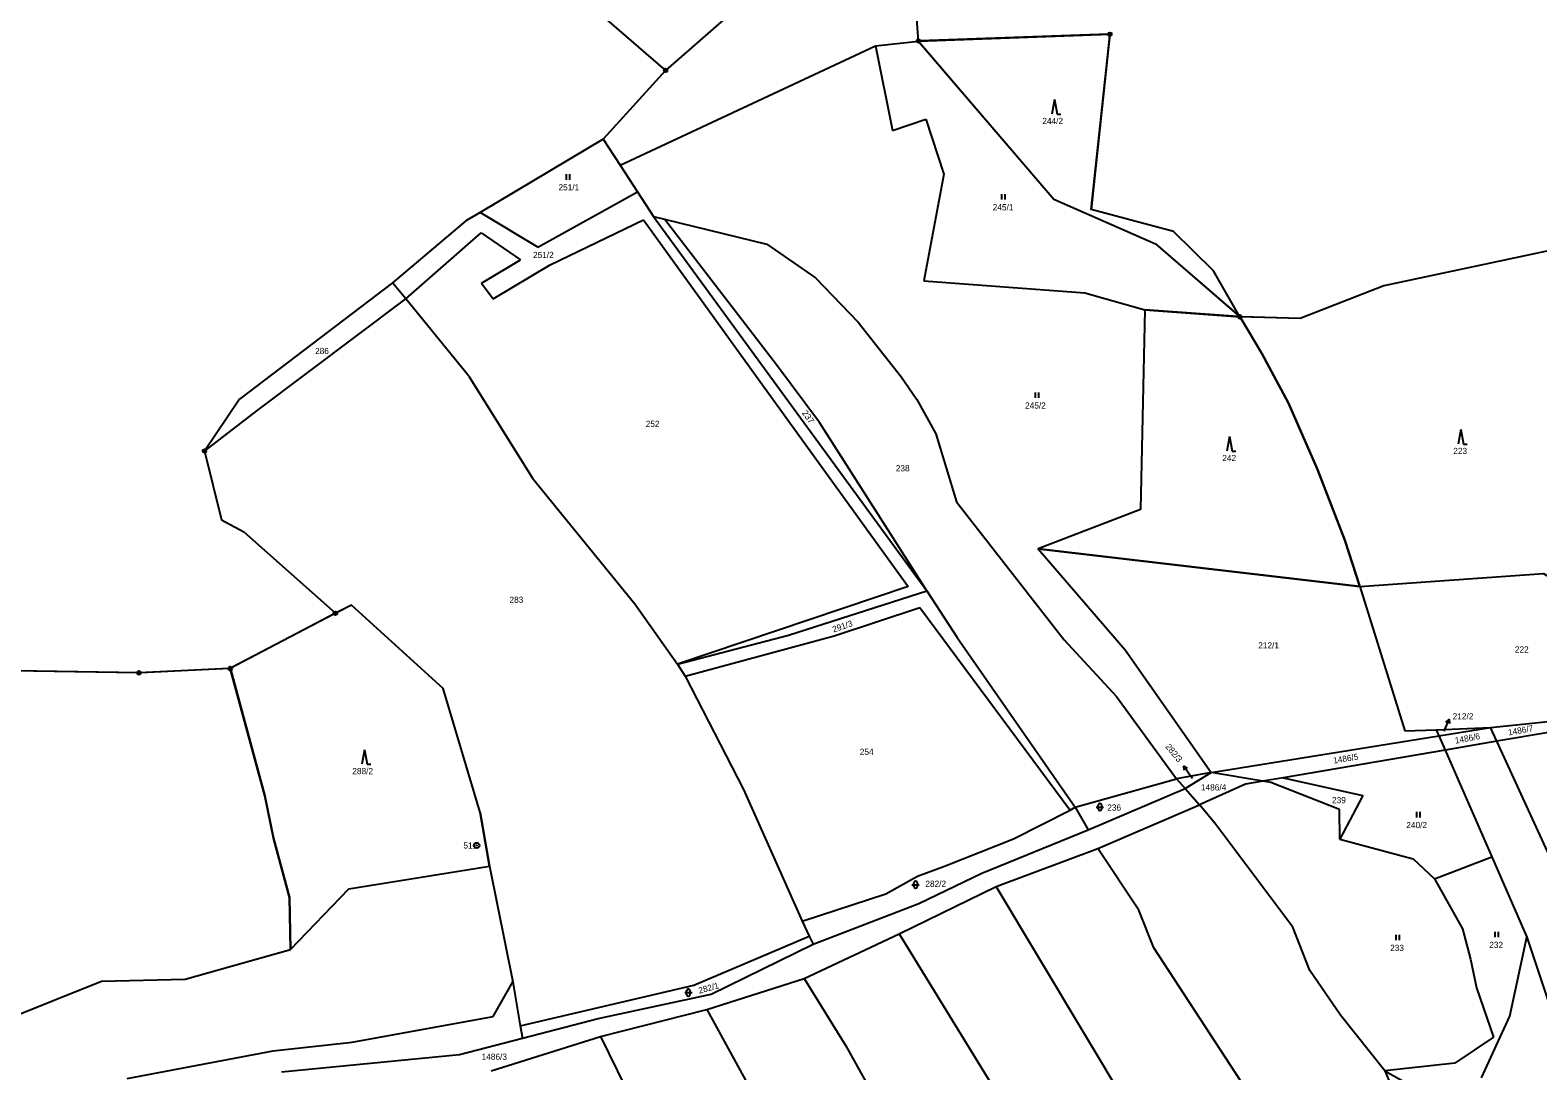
# Model space of a CAD drawing. Extents: x -760642 to -757221, y -1092371 to -1088855.
# Drawn here: x -759009.6 to -758595.9, y -1089386.3 to -1089100.6 of the extents above; entities that cross this region are included whole.
import ezdxf

# ---------------------------------------------------------------- set-up
doc = ezdxf.new("R2010")
doc.units = 0
for name, color, linetype in [('Vrstva 1', 7, 'Continuous'), ('Vrstva 13', 7, 'Continuous'), ('Vrstva 16', 7, 'Continuous'), ('Vrstva 17', 7, 'Continuous'), ('Vrstva 18', 7, 'Continuous'), ('Vrstva 24', 7, 'Continuous'), ('Vrstva 25', 7, 'Continuous'), ('Vrstva 30', 7, 'Continuous')]:
    doc.layers.add(name, color=color, linetype=linetype)

msp = doc.modelspace()

# ---------------------------------------------------------------- linework, layer by layer
at = {"layer": 'Vrstva 1'}
for p, q in [((-758806.96, -1089086.83), (-758835.2, -1089111.71)), ((-758847.72, -1089137.73), (-758777.58, -1089104.93)), ((-758777.58, -1089104.93), (-758765.86, -1089103.63)), ((-758777.58, -1089104.93), (-758772.95, -1089128.17)), ((-758765.86, -1089103.63), (-758728.69, -1089147.07)), ((-758772.95, -1089128.17), (-758763.77, -1089125.06)), ((-758763.77, -1089125.06), (-758758.83, -1089140.17)), ((-758852.39, -1089130.57), (-758847.72, -1089137.73)), ((-758847.72, -1089137.73), (-758842.96, -1089145.03)), ((-758758.83, -1089140.17), (-758764.34, -1089169.41)), ((-758870.25, -1089160.21), (-758842.96, -1089145.03)), ((-758842.96, -1089145.03), (-758838.55, -1089151.8)), ((-758728.69, -1089147.07), (-758700.81, -1089159.29)), ((-758870.25, -1089160.21), (-758886.09, -1089150.66)), ((-758866.92, -1089165.08), (-758841.31, -1089152.72)), ((-758841.31, -1089152.72), (-758809.38, -1089197)), ((-758838.55, -1089151.8), (-758835.54, -1089152.54)), ((-758838.55, -1089151.8), (-758763.58, -1089254.51)), ((-758835.54, -1089152.54), (-758807.4, -1089159.43)), ((-758804.82, -1089192.51), (-758835.54, -1089152.54)), ((-758906.54, -1089174.42), (-758885.79, -1089156.32)), ((-758885.79, -1089156.32), (-758875.06, -1089163.7)), ((-758807.4, -1089159.43), (-758794.13, -1089168.66)), ((-758700.81, -1089159.29), (-758677.66, -1089179.3)), ((-758885.71, -1089170.11), (-758875.06, -1089163.7)), ((-758882.49, -1089174.37), (-758866.92, -1089165.08)), ((-758906.54, -1089174.42), (-758910.14, -1089169.98)), ((-758885.71, -1089170.11), (-758882.49, -1089174.37)), ((-758794.13, -1089168.66), (-758782.42, -1089180.77)), ((-758764.34, -1089169.41), (-758720.16, -1089172.73)), ((-758947.37, -1089205.09), (-758906.54, -1089174.42)), ((-758889.22, -1089195.64), (-758906.54, -1089174.42)), ((-758720.16, -1089172.73), (-758703.71, -1089177.42)), ((-758703.71, -1089177.42), (-758704.9, -1089232.18)), ((-758703.71, -1089177.42), (-758677.66, -1089179.3)), ((-758677.66, -1089179.3), (-758671.58, -1089189.42)), ((-758782.42, -1089180.77), (-758770.45, -1089195.87)), ((-758793.02, -1089208.3), (-758804.82, -1089192.51)), ((-758671.58, -1089189.42), (-758664.26, -1089203.07)), ((-758889.22, -1089195.64), (-758871.78, -1089223.66)), ((-758770.45, -1089195.87), (-758766.28, -1089201.98)), ((-758809.38, -1089197), (-758768.62, -1089253.32)), ((-758961.77, -1089216.17), (-758947.37, -1089205.09)), ((-758766.28, -1089201.98), (-758761.08, -1089211.48)), ((-758664.26, -1089203.07), (-758656.38, -1089221.23)), ((-758763.58, -1089254.51), (-758793.02, -1089208.3)), ((-758761.08, -1089211.48), (-758755.35, -1089230.09)), ((-758656.38, -1089221.23), (-758648.84, -1089240.6)), ((-758871.78, -1089223.66), (-758843.69, -1089258.12)), ((-758755.35, -1089230.09), (-758725.84, -1089268)), ((-758704.9, -1089232.18), (-758732.99, -1089242.97)), ((-758648.84, -1089240.6), (-758644.74, -1089253.34)), ((-758644.74, -1089253.34), (-758732.99, -1089242.97)), ((-758732.99, -1089242.97), (-758709.08, -1089270.75)), ((-758644.74, -1089253.34), (-758594.33, -1089249.82)), ((-758768.62, -1089253.32), (-758831.96, -1089274.7)), ((-758801.49, -1089266.7), (-758763.58, -1089254.51)), ((-758763.58, -1089254.51), (-758755.18, -1089267.31)), ((-758644.74, -1089253.34), (-758632.34, -1089292.95)), ((-758921.36, -1089258.49), (-758925.81, -1089260.68)), ((-758896.27, -1089281.34), (-758921.36, -1089258.49)), ((-758843.69, -1089258.12), (-758831.96, -1089274.7)), ((-758789, -1089266.9), (-758765.5, -1089259.15)), ((-758765.5, -1089259.15), (-758724.18, -1089314.77)), ((-758831.96, -1089274.7), (-758801.49, -1089266.7)), ((-758829.82, -1089277.96), (-758789, -1089266.9)), ((-758755.18, -1089267.31), (-758722.83, -1089313.91)), ((-758725.84, -1089268), (-758711.49, -1089283.54)), ((-758709.08, -1089270.75), (-758685.49, -1089304.37)), ((-758831.96, -1089274.7), (-758829.82, -1089277.96)), ((-758945.22, -1089310.83), (-758954.69, -1089275.84)), ((-758829.82, -1089277.96), (-758813.85, -1089309.1)), ((-758886.08, -1089315.4), (-758896.27, -1089281.34)), ((-758711.49, -1089283.54), (-758695.03, -1089306.11)), ((-758623.76, -1089292.69), (-758608.87, -1089292.02)), ((-758623.05, -1089294.31), (-758608.87, -1089292.02)), ((-758608.87, -1089292.02), (-758593.08, -1089290.4)), ((-758607.09, -1089295.84), (-758608.87, -1089292.02)), ((-758685.49, -1089304.37), (-758623.05, -1089294.31)), ((-758632.34, -1089292.95), (-758623.76, -1089292.69)), ((-758623.76, -1089292.69), (-758623.05, -1089294.31)), ((-758623.05, -1089294.31), (-758621.32, -1089298.27)), ((-758607.09, -1089295.84), (-758621.32, -1089298.27)), ((-758591.9, -1089293.25), (-758607.09, -1089295.84)), ((-758578.14, -1089359.07), (-758607.09, -1089295.84)), ((-758621.32, -1089298.27), (-758665.79, -1089305.87)), ((-758621.32, -1089298.27), (-758608.54, -1089327.54)), ((-758685.49, -1089304.37), (-758695.03, -1089306.11)), ((-758692.67, -1089308.78), (-758685.49, -1089304.37)), ((-758671.3, -1089306.81), (-758685.49, -1089304.37)), ((-758722.83, -1089313.91), (-758695.03, -1089306.11)), ((-758695.03, -1089306.11), (-758692.67, -1089308.78)), ((-758676.07, -1089307.62), (-758688.72, -1089313.31)), ((-758671.3, -1089306.81), (-758676.07, -1089307.62)), ((-758665.79, -1089305.87), (-758671.3, -1089306.81)), ((-758669.17, -1089307.17), (-758671.3, -1089306.81)), ((-758650.27, -1089314.52), (-758669.17, -1089307.17)), ((-758665.79, -1089305.87), (-758643.89, -1089310.74)), ((-758942.82, -1089322.44), (-758945.22, -1089310.83)), ((-758813.85, -1089309.1), (-758797.77, -1089345.22)), ((-758719.25, -1089320.18), (-758692.67, -1089308.78)), ((-758692.67, -1089308.78), (-758688.72, -1089313.31)), ((-758643.89, -1089310.74), (-758650.21, -1089322.73)), ((-758886.08, -1089315.4), (-758883.53, -1089330.13)), ((-758739.77, -1089322.64), (-758724.18, -1089314.77)), ((-758724.18, -1089314.77), (-758722.83, -1089313.91)), ((-758722.83, -1089313.91), (-758719.25, -1089320.18)), ((-758716.63, -1089325.27), (-758688.72, -1089313.31)), ((-758684.55, -1089318.34), (-758688.72, -1089313.31)), ((-758650.21, -1089322.73), (-758650.27, -1089314.52)), ((-758748.43, -1089332.07), (-758719.25, -1089320.18)), ((-758663.08, -1089346.84), (-758684.55, -1089318.34)), ((-758938.46, -1089338.67), (-758942.82, -1089322.44)), ((-758758.67, -1089330.1), (-758739.77, -1089322.64)), ((-758650.21, -1089322.73), (-758630.08, -1089328.14)), ((-758744.55, -1089335.69), (-758716.63, -1089325.27)), ((-758705.4, -1089342.16), (-758716.63, -1089325.27)), ((-758630.08, -1089328.14), (-758624.28, -1089333.59)), ((-758624.28, -1089333.59), (-758608.54, -1089327.54)), ((-758608.54, -1089327.54), (-758598.93, -1089349.56)), ((-758922.13, -1089336.32), (-758883.53, -1089330.13)), ((-758883.53, -1089330.13), (-758877.13, -1089361.88)), ((-758774.77, -1089337.68), (-758766.12, -1089332.89)), ((-758766.12, -1089332.89), (-758758.67, -1089330.1)), ((-758765.73, -1089340.33), (-758748.43, -1089332.07)), ((-758938.12, -1089353.02), (-758922.13, -1089336.32)), ((-758771.14, -1089348.64), (-758744.55, -1089335.69)), ((-758703.81, -1089403.61), (-758744.55, -1089335.69)), ((-758624.28, -1089333.59), (-758616.57, -1089347.27)), ((-758938.12, -1089353.02), (-758938.46, -1089338.67)), ((-758797.77, -1089345.22), (-758774.77, -1089337.68)), ((-758794.75, -1089351.56), (-758765.73, -1089340.33)), ((-758797.77, -1089345.22), (-758795.81, -1089349.34)), ((-758701.29, -1089352.57), (-758705.4, -1089342.16)), ((-758827.46, -1089362.79), (-758795.81, -1089349.34)), ((-758797.2, -1089360.9), (-758771.14, -1089348.64)), ((-758795.81, -1089349.34), (-758794.75, -1089351.56)), ((-758771.14, -1089348.64), (-758744.55, -1089392.09)), ((-758658.44, -1089358.77), (-758663.08, -1089346.84)), ((-758616.57, -1089347.27), (-758614.33, -1089355.59)), ((-758603.59, -1089371.32), (-758598.93, -1089349.56)), ((-758598.93, -1089349.56), (-758590.19, -1089375.63)), ((-758967.09, -1089361.14), (-758938.12, -1089353.02)), ((-758822.69, -1089365.28), (-758794.75, -1089351.56)), ((-758671.52, -1089398.05), (-758701.29, -1089352.57)), ((-758614.33, -1089355.59), (-758612.74, -1089363.49)), ((-759016.87, -1089372.48), (-758989.96, -1089361.68)), ((-758989.96, -1089361.68), (-758967.09, -1089361.14)), ((-758882.49, -1089371.34), (-758877.13, -1089361.88)), ((-758877.13, -1089361.88), (-758875.08, -1089373.94)), ((-758823.94, -1089369.43), (-758797.2, -1089360.9)), ((-758797.2, -1089360.9), (-758785.74, -1089379.46)), ((-758650, -1089370.96), (-758658.44, -1089358.77)), ((-758875.08, -1089373.94), (-758827.46, -1089362.79)), ((-758853.69, -1089371.88), (-758822.69, -1089365.28)), ((-758612.74, -1089363.49), (-758608.08, -1089377.05)), ((-758853.05, -1089376.83), (-758823.94, -1089369.43)), ((-758823.94, -1089369.43), (-758779.56, -1089450.18)), ((-758921.25, -1089378.45), (-758882.49, -1089371.34)), ((-758875.08, -1089373.94), (-758874.51, -1089377.29)), ((-758874.51, -1089377.29), (-758853.69, -1089371.88)), ((-758637.85, -1089386.28), (-758650, -1089370.96)), ((-758611.31, -1089388.19), (-758603.59, -1089371.32)), ((-758942.91, -1089380.82), (-758921.25, -1089378.45)), ((-758891.8, -1089381.78), (-758874.51, -1089377.29)), ((-758883.06, -1089386.31), (-758853.05, -1089376.83)), ((-758853.05, -1089376.83), (-758830.77, -1089422.32)), ((-758608.08, -1089377.05), (-758618.64, -1089384.22)), ((-758982.96, -1089388.36), (-758942.91, -1089380.82)), ((-758940.61, -1089386.57), (-758891.8, -1089381.78)), ((-758785.74, -1089379.46), (-758760.41, -1089424.72)), ((-758618.64, -1089384.22), (-758637.85, -1089386.28)), ((-758637.85, -1089386.28), (-758622, -1089395.14)), ((-758637.85, -1089386.28), (-758617.78, -1089434.32))]:
    msp.add_line(p, q, dxfattribs=at)
at = {"layer": 'Vrstva 13'}
for p, q in [((-758765.86, -1089103.63), (-758768.37, -1089067.76)), ((-758864.44, -1089086.48), (-758835.2, -1089111.71)), ((-758765.86, -1089103.63), (-758713.31, -1089101.77)), ((-758713.31, -1089101.77), (-758718.42, -1089149.83)), ((-758835.2, -1089111.71), (-758852.39, -1089130.57)), ((-758852.39, -1089130.57), (-758886.09, -1089150.66)), ((-758886.09, -1089150.66), (-758889.99, -1089152.99)), ((-758695.85, -1089155.89), (-758718.42, -1089149.83)), ((-758889.99, -1089152.99), (-758910.14, -1089169.98)), ((-758684.84, -1089166.7), (-758695.85, -1089155.89)), ((-758592.14, -1089161.06), (-758638.18, -1089170.81)), ((-758677.66, -1089179.3), (-758684.84, -1089166.7)), ((-758910.14, -1089169.98), (-758952.14, -1089201.9)), ((-758638.18, -1089170.81), (-758661.09, -1089179.82)), ((-758661.09, -1089179.82), (-758677.66, -1089179.3)), ((-758952.14, -1089201.9), (-758961.77, -1089216.17)), ((-758961.77, -1089216.17), (-758957.11, -1089235.03)), ((-758957.11, -1089235.03), (-758950.91, -1089238.38)), ((-758950.91, -1089238.38), (-758925.81, -1089260.68)), ((-758925.81, -1089260.68), (-758954.69, -1089275.84)), ((-758979.74, -1089277.04), (-759077.5, -1089275.49)), ((-758954.69, -1089275.84), (-758979.74, -1089277.04))]:
    msp.add_line(p, q, dxfattribs=at)
at = {"layer": 'Vrstva 16'}
for p, q in [((-758621.36, -1089292.61), (-758620.256, -1089289.82)), ((-758621.53, -1089293.03), (-758621.36, -1089292.61)), ((-758691.34, -1089305.1), (-758693.057, -1089302.64)), ((-758690.66, -1089306.08), (-758691.34, -1089305.1))]:
    msp.add_line(p, q, dxfattribs=at)
for points in [[(-758621.089, -1089290.566), (-758620.256, -1089289.82), (-758620.159, -1089290.934)], [(-758692.894, -1089303.746), (-758693.057, -1089302.64), (-758692.074, -1089303.174)]]:
    msp.add_lwpolyline(points, dxfattribs=at)
at = {"layer": 'Vrstva 24'}
for centre, radius in [((-758713.31, -1089101.77), 0.5), ((-758713.31, -1089101.77), 0.0327), ((-758765.86, -1089103.63), 0.5), ((-758765.86, -1089103.63), 0.5), ((-758765.86, -1089103.63), 0.0327), ((-758765.86, -1089103.63), 0.0327), ((-758835.2, -1089111.71), 0.5), ((-758835.2, -1089111.71), 0.0327), ((-758677.66, -1089179.3), 0.5), ((-758677.66, -1089179.3), 0.5), ((-758677.66, -1089179.3), 0.0327), ((-758677.66, -1089179.3), 0.0327), ((-758961.77, -1089216.17), 0.5), ((-758961.77, -1089216.17), 0.0327), ((-758925.81, -1089260.68), 0.5), ((-758925.81, -1089260.68), 0.0327), ((-758954.69, -1089275.84), 0.5), ((-758954.69, -1089275.84), 0.5), ((-758979.74, -1089277.04), 0.5), ((-758979.74, -1089277.04), 0.5), ((-758979.74, -1089277.04), 0.0327), ((-758979.74, -1089277.04), 0.0327), ((-758954.69, -1089275.84), 0.0327), ((-758954.69, -1089275.84), 0.0327), ((-758887.05, -1089324.42), 0.75), ((-758887.05, -1089324.42), 0.0327)]:
    msp.add_circle(centre, radius, dxfattribs=at)
at = {"layer": 'Vrstva 25'}
for p, q in [((-758728.542, -1089119.709), (-758729.275, -1089123.709)), ((-758728.542, -1089119.709), (-758727.809, -1089123.709)), ((-758727.809, -1089123.709), (-758726.809, -1089123.709)), ((-758862.507, -1089140.195), (-758862.507, -1089141.695)), ((-758861.485, -1089141.695), (-758861.485, -1089140.195)), ((-758743.047, -1089145.675), (-758743.047, -1089147.175)), ((-758742.025, -1089147.175), (-758742.025, -1089145.675)), ((-758733.797, -1089200.085), (-758733.797, -1089201.585)), ((-758732.775, -1089201.585), (-758732.775, -1089200.085)), ((-758680.472, -1089212.219), (-758681.205, -1089216.219)), ((-758680.472, -1089212.219), (-758679.739, -1089216.219)), ((-758617.022, -1089210.289), (-758617.755, -1089214.289)), ((-758617.022, -1089210.289), (-758616.289, -1089214.289)), ((-758679.739, -1089216.219), (-758678.739, -1089216.219)), ((-758616.289, -1089214.289), (-758615.289, -1089214.289)), ((-758917.832, -1089298.149), (-758918.565, -1089302.149)), ((-758917.832, -1089298.149), (-758917.099, -1089302.149)), ((-758917.099, -1089302.149), (-758916.099, -1089302.149)), ((-758717.03, -1089313.87), (-758715.03, -1089313.87)), ((-758716.53, -1089314.37), (-758716.53, -1089313.37)), ((-758715.53, -1089314.37), (-758715.53, -1089313.37)), ((-758629.207, -1089315.235), (-758629.207, -1089316.735)), ((-758628.185, -1089316.735), (-758628.185, -1089315.235)), ((-758767.61, -1089335.19), (-758765.61, -1089335.19)), ((-758767.11, -1089335.69), (-758767.11, -1089334.69)), ((-758766.11, -1089335.69), (-758766.11, -1089334.69)), ((-758634.887, -1089348.955), (-758634.887, -1089350.455)), ((-758633.865, -1089350.455), (-758633.865, -1089348.955)), ((-758607.697, -1089348.135), (-758607.697, -1089349.635)), ((-758606.675, -1089349.635), (-758606.675, -1089348.135)), ((-758829.97, -1089364.81), (-758827.97, -1089364.81)), ((-758829.47, -1089365.31), (-758829.47, -1089364.31)), ((-758828.47, -1089365.31), (-758828.47, -1089364.31))]:
    msp.add_line(p, q, dxfattribs=at)
for centre, start, end in [((-758716.03, -1089313.37), 0, 180), ((-758716.03, -1089314.37), 180, 0), ((-758766.61, -1089334.69), 0, 180), ((-758766.61, -1089335.69), 180, 0), ((-758828.97, -1089364.31), 0, 180), ((-758828.97, -1089365.31), 180, 0)]:
    msp.add_arc(centre, 0.5, start, end, dxfattribs=at)
at = {"layer": 'Vrstva 30'}
for points in [[(-758713.81, -1089101.788), (-758765.36, -1089103.612)], [(-758765.535, -1089104.01), (-758728.69, -1089147.07), (-758700.81, -1089159.29), (-758678.038, -1089178.973)], [(-758677.908, -1089178.866), (-758684.84, -1089166.7), (-758695.85, -1089155.89), (-758718.42, -1089149.83), (-758713.363, -1089102.267)], [(-758677.403, -1089179.729), (-758671.58, -1089189.42), (-758664.26, -1089203.07), (-758656.38, -1089221.23), (-758648.84, -1089240.6), (-758644.74, -1089253.34), (-758594.33, -1089249.82), (-758582.08, -1089257.06), (-758568.43, -1089249.17), (-758592.01, -1089161.543), (-758592.14, -1089161.06), (-758638.18, -1089170.81), (-758661.09, -1089179.82), (-758677.16, -1089179.316)], [(-758678.159, -1089179.264), (-758703.71, -1089177.42), (-758704.9, -1089232.18), (-758732.99, -1089242.97), (-758644.74, -1089253.34), (-758648.84, -1089240.6), (-758656.38, -1089221.23), (-758664.26, -1089203.07), (-758671.58, -1089189.42), (-758677.403, -1089179.729)], [(-758954.559, -1089276.323), (-758945.22, -1089310.83), (-758942.82, -1089322.44), (-758938.46, -1089338.67), (-758938.12, -1089353.02), (-758922.13, -1089336.32), (-758883.53, -1089330.13), (-758886.08, -1089315.4), (-758896.27, -1089281.34), (-758921.36, -1089258.49), (-758925.361, -1089260.459)], [(-758926.253, -1089260.912), (-758954.247, -1089275.608)], [(-759260.604, -1089266.083), (-759261.13, -1089269.16), (-759262.38, -1089276.56), (-759244.75, -1089308.25), (-759118.13, -1089341.69), (-759091.99, -1089341), (-759071.08, -1089368.72), (-759046.58, -1089377.41), (-759016.87, -1089372.48), (-758989.96, -1089361.68), (-758967.09, -1089361.14), (-758938.12, -1089353.02), (-758938.46, -1089338.67), (-758942.82, -1089322.44), (-758945.22, -1089310.83), (-758954.559, -1089276.323)], [(-758980.24, -1089277.032), (-759077, -1089275.498)], [(-758955.189, -1089275.864), (-758979.241, -1089277.016)]]:
    msp.add_lwpolyline(points, dxfattribs=at)
for centre, start, end in [((-758713.31, -1089101.77), 182.02713, 263.9308), ((-758765.86, -1089103.63), 310.55238, 0), ((-758765.86, -1089103.63), 0, 2.02713), ((-758677.66, -1089179.3), 175.87218, 180), ((-758677.66, -1089179.3), 180, 300.99705), ((-758677.66, -1089179.3), 119.67628, 139.16108), ((-758677.66, -1089179.3), 300.99705, 358.20253), ((-758925.81, -1089260.68), 207.69636, 0), ((-758925.81, -1089260.68), 0, 26.20341), ((-758979.74, -1089277.04), 179.09164, 180), ((-758979.74, -1089277.04), 180, 0), ((-758979.74, -1089277.04), 0, 2.74261), ((-758954.69, -1089275.84), 182.74261, 285.14421), ((-758954.69, -1089275.84), 285.14421, 0), ((-758954.69, -1089275.84), 0, 27.69636)]:
    msp.add_arc(centre, 0.5, start, end, dxfattribs=at)

# ---------------------------------------------------------------- texts
at = {"layer": 'Vrstva 16'}
msp.add_text('212/2', height=1.7, dxfattribs=at).set_placement((-758619.26, -1089289.82))
msp.add_text('282/3', height=1.7, rotation=309.26898, dxfattribs=at).set_placement((-758698.196, -1089297.353))
at = {"layer": 'Vrstva 17'}
msp.add_text('511', height=1.7, dxfattribs=at).set_placement((-758890.695, -1089325.27))
at = {"layer": 'Vrstva 18'}
for s, height, p in [('244/2', 1.7, (-758731.839, -1089126.42)), ('251/1', 1.7, (-758864.61, -1089144.63)), ('245/1', 1.7, (-758745.46, -1089150.11)), ('251/2', 1.7, (-758871.6, -1089163.2)), ('286', 1.7, (-758931.4, -1089189.56)), ('245/2', 1.7, (-758736.58, -1089204.52)), ('252', 1.7, (-758840.68, -1089209.56)), ('242', 1.7, (-758682.46, -1089218.93)), ('223', 1.7, (-758619.09, -1089217)), ('238', 1.7, (-758772.05, -1089221.74)), ('283', 1.7, (-758878.05, -1089257.84)), ('212/1', 1.7, (-758672.6, -1089270.35)), ('222', 1.7, (-758602.17, -1089271.48)), ('212/2', 0.1, (-758621.666, -1089293.03)), ('254', 1.7, (-758781.94, -1089299.56)), ('288/2', 1.7, (-758921.18, -1089304.86)), ('282/3', 0.1, (-758690.812, -1089306.08)), ('1486/4', 1.7, (-758688.33, -1089309.33)), ('239', 1.7, (-758652.336, -1089312.82)), ('236', 1.7, (-758714.03, -1089314.87)), ('240/2', 1.7, (-758631.972, -1089319.67)), ('282/2', 1.7, (-758763.94, -1089335.8)), ('233', 1.7, (-758636.41, -1089353.39)), ('232', 1.7, (-758609.21, -1089352.57)), ('1486/3', 1.7, (-758885.7, -1089383.26))]:
    msp.add_text(s, height=height, dxfattribs=at).set_placement(p)
for s, rotation, p in [('237', 305.32374, (-758797.89, -1089205.73)), ('291/3', 18.49392, (-758789.13, -1089266)), ('1486/7', 9.88173, (-758603.9, -1089294.26)), ('1486/6', 10.66752, (-758618.47, -1089296.5)), ('1486/5', 9.2745, (-758651.89, -1089301.98)), ('282/1', 15.49926, (-758825.93, -1089365.12))]:
    msp.add_text(s, height=1.7, rotation=rotation, dxfattribs=at).set_placement(p)

doc.saveas('drawing.dxf')
